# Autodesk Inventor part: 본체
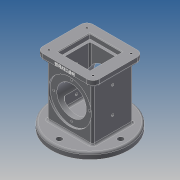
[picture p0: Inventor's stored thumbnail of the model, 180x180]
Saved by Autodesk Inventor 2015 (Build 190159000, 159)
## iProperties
Created: 2018-10
Part Number: 본체
Material: 일반
Document SubType Name: Modeling
Designer: user
Density: 1 g/cm^3
Appearance: 기본값
Author: user
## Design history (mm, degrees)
sketch "스케치1"
  geometry: C1 r 62.5 at (0, 0); 1 further point
  constraints: 1 centre point, 1 coincident
  dimensions: "d0" = 125 diameter of C1
extrude "돌출1" new body sketch "스케치1" distance "d1" = 10; taper "d2" = 0 deg
sketch "스케치2"
  geometry: L1 (-37, -33)-(37, -33); L2 (37, -33)-(37, 33); L3 (37, 33)-(-37, 33); L4 (-37, 33)-(-37, -33); L5 (-37, -33)-(37, 33); L6 (37, -33)-(-37, 33); C1 r 62.5 at (0, 0) reference
  constraints: 12 end point, 2 midpoint, 2 parallel, 1 horizontal, 1 perpendicular
  dimensions: "d3" = 74 distance of L3.end L2.end; "d4" = 66 distance of L2.end L1.end
extrude "돌출2" join sketch "스케치2" distance "d5" = 88; taper "d6" = 0 deg
sketch "스케치3"
  geometry: L1 (46, -41)-(-46, -41); L2 (-46, -41)-(-46, 41); L3 (-46, 41)-(46, 41); L4 (46, 41)-(46, -41); L5 (46, -41)-(-46, 41); L6 (-46, -41)-(46, 41); 1 further point
  constraints: 12 end point, 2 midpoint, 2 parallel, 1 horizontal, 1 perpendicular
  dimensions: "d7" = 92 distance of L2.end L3.end; "d8" = 82 distance of L3.end L1.start
extrude "돌출3" join sketch "스케치3" distance "d9" = 10; taper "d10" = 0 deg
sketch "스케치4"
  geometry: L1 (-26, -26)-(26, -26); L2 (26, -26)-(26, 26); L3 (26, 26)-(-26, 26); L4 (-26, 26)-(-26, -26); L5 (-26, -26)-(26, 26); L6 (26, -26)-(-26, 26); 1 further point
  constraints: 12 end point, 2 midpoint, 2 parallel, 1 horizontal, 1 perpendicular
  dimensions: "d11" = 52 distance of L3.end L2.end; "d12" = 52 distance of L2.end L1.end
extrude "돌출4" cut sketch "스케치4" distance "d13" = 8; taper "d14" = 0 deg
sketch "스케치5"
  geometry: L1 (-25.5, -10)-(99.5, -10) reference; C1 r 35 at (37, 44); 1 further point
  constraints: 1 centre point
  dimensions: "d15" = 54 distance from line of L1 C1.centre; "d16" = 70 diameter of C1
extrude "돌출5" cut sketch "스케치5" distance "d17" = 3; taper "d18" = 0 deg
sketch "스케치6"
  geometry: C1 r 35 at (0, 0) reference; C2 r 24 at (0, 0); 1 further point
  constraints: 1 centre point, 1 coincident
  dimensions: "d19" = 48 diameter of C2
extrude "돌출6" cut sketch "스케치6" stored distance "d20" = 3; taper "d21" = 0 deg
sketch "스케치7"
  geometry: L1 (-22, -22)-(22, -22); L2 (22, -22)-(22, 22); L3 (22, 22)-(-22, 22); L4 (-22, 22)-(-22, -22); L5 (-22, -22)-(22, 22); L6 (22, -22)-(-22, 22); 1 further point
  constraints: 12 end point, 2 midpoint, 2 parallel, 1 horizontal, 1 perpendicular
  dimensions: "d22" = 44 distance of L3.end L2.end; "d23" = 44 distance of L2.end L1.end
extrude "돌출7" cut sketch "스케치7" distance "d24" = 74; taper "d25" = 0 deg
chamfer "모따기1" distance "d26" = 1; stored, may be unused: second distance "d27" = 2, angle "d28" = 45 deg
sketch "스케치9"
  geometry: C1 r 62.5 at (0, 0) reference; C2 r 28 at (0, 0)
  constraints: 1 centre point, 1 coincident
  dimensions: "d29" = 56 diameter of C2
extrude "돌출8" cut sketch "스케치9" distance "d30" = 18; taper "d31" = -10 deg
sketch "스케치10"
  geometry: L1 (10, 33)-(-27, 33); L2 (-27, 33)-(-70, 33); 2 further points
  constraints: 4 end point, 2 coincident, 1 horizontal, 1 point on line
  dimensions: "d32" = 37 distance of L1.start L1.end; "d33" = 43 distance of L1.end L2.end
hole "구멍1" sketch "스케치10" at (-70, 33), (-27, 33) diameter "d34" = 4.134; stored, may be unused: countersink angle "d38" = 90 deg, drill point angle "d40" = 118 deg; dims "d35" = 10, "d36" = 4, "d37" = 2, "d39" = 14.2
sketch "스케치11"
  geometry: C1 r 24 at (0, 0) reference; C2 r 35 at (0, 0) reference; A1 r 29 centre (0, 0) between (0, 29) and (-29, 0); 3 further points
  constraints: 4 point on circle, 2 horizontal alignment, 2 vertical alignment, 1 centre point, 1 coincident
  dimensions: "d41" = 58 diameter of A1
hole "구멍2" sketch "스케치11" at (0, 29), (-29, 0), (0, -29), (29, 0) diameter "d42" = 3.242; stored, may be unused: countersink angle "d46" = 90 deg, drill point angle "d48" = 118 deg; dims "d43" = 4, "d44" = 4, "d45" = 2, "d47" = 6
sketch "스케치12"
  geometry: C1 r 62.5 at (0, 0) reference; A1 r 50 centre (0, 0) between (0, 50) and (-50, 0); 2 further points
  constraints: 4 point on circle, 2 horizontal alignment, 2 vertical alignment, 1 centre point, 1 coincident
  dimensions: "d49" = 100 diameter of A1
hole "구멍3" sketch "스케치12" at (0, 50), (-50, 0), (0, -50), (50, 0) diameter "d50" = 9; stored, may be unused: countersink angle "d54" = 90 deg, drill point angle "d56" = 118 deg; dims "d51" = 4, "d52" = 4, "d53" = 2, "d55" = 6
sketch "스케치13"
  geometry: L1 (36, -31)-(-36, -31); L2 (-36, -31)-(-36, 31); L3 (-36, 31)-(36, 31); L4 (36, 31)-(36, -31); L5 (36, -31)-(-36, 31); L6 (-36, -31)-(36, 31); 5 further points
  constraints: 12 end point, 4 coincident, 2 midpoint, 2 parallel, 1 horizontal, 1 perpendicular
  dimensions: "d57" = 72 distance of L2.end L3.end; "d58" = 62 distance of L3.end L1.start
hole "구멍4" sketch "스케치13" at (-36, 31), (-36, -31), (36, -31), (36, 31) diameter "d59" = 3.242; stored, may be unused: countersink angle "d63" = 90 deg, drill point angle "d65" = 118 deg; dims "d60" = 4, "d61" = 4, "d62" = 2, "d64" = 6
fillet "모깎기1" dims "d66" = 10
fillet "모깎기2" dims "d67" = 3
fillet "모깎기3" dims "d68" = 3
fillet "모깎기4" dims "d69" = 3
fillet "모깎기5" dims "d70" = 3
fillet "모깎기6" dims "d71" = 3
fillet "모깎기7" dims "d72" = 3
fillet "모깎기8" dims "d73" = 3
fillet "모깎기9" dims "d74" = 3
sketch "스케치14"
  geometry: L1 (0, 0)-(72, 0) reference; L2 (-10, 0)-(-10, -7) reference; 2 further points
  constraints: 1 other
  dimensions: "d75" = 46 distance from line of point (36, -4) L2; "d76" = 4 distance from line of L1 point (36, -4)
feature "엠보싱1" sketch "스케치14" dims "d2" = 0, "d10" = 0, "d77" = 0.5, "d78" = 0
node "솔리드1"
mirror "대칭1"
mirror "대칭2"
